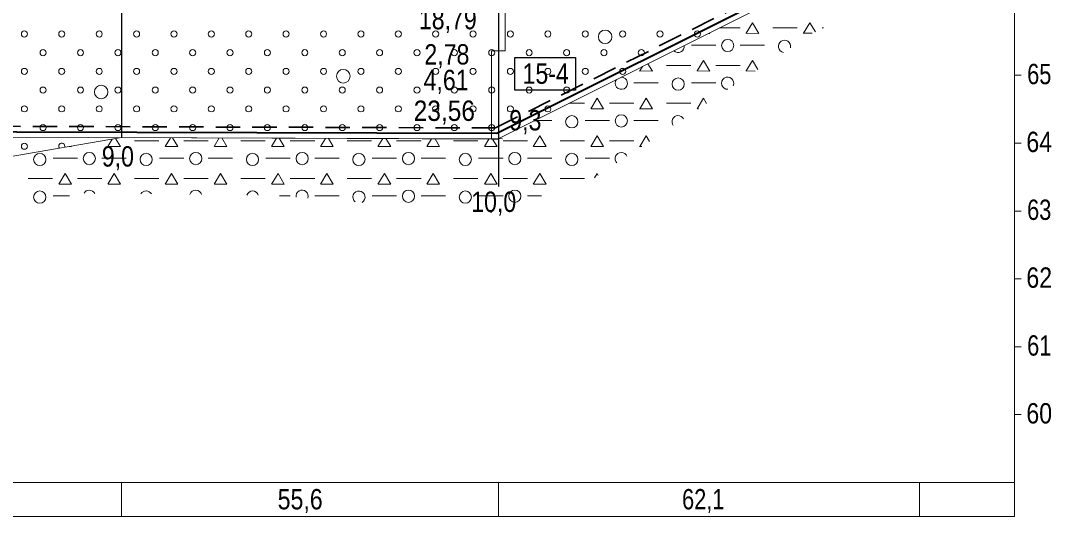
# Model space of a CAD drawing. Extents: x 640121 to 640955, y 6441885 to 6442246.
# Drawn here: x 640363.9 to 640515.9, y 6442063 to 6442136.1 of the extents above; entities that cross this region are included whole.
import ezdxf
from ezdxf.enums import TextEntityAlignment as Align

# ---------------------------------------------------------------- set-up
doc = ezdxf.new("R2010")
doc.units = 0
doc.header["$LTSCALE"] = 1.2
doc.linetypes.add('MEDIUM_DASHED', pattern=[4.5, 3, -1.5])
for name, color, linetype, lineweight in [('30', 7, 'Continuous', 13), ('31', 7, 'Continuous', 13), ('32', 7, 'Continuous', 13), ('33', 7, 'Continuous', 13), ('35', 7, 'Continuous', 35), ('42', 7, 'Continuous', 13), ('46', 7, 'Continuous', 13), ('47', 7, 'Continuous', 13)]:
    doc.layers.add(name, color=color, linetype=linetype, lineweight=lineweight)

msp = doc.modelspace()

# ---------------------------------------------------------------- linework, layer by layer
at = {"layer": '30'}
for p, q in [((640510.5, 6442063), (640510.5, 6442218)), ((640510.5, 6442128), (640511.5, 6442128)), ((640510.5, 6442118), (640511.5, 6442118)), ((640510.5, 6442108), (640511.5, 6442108)), ((640510.5, 6442098), (640511.5, 6442098)), ((640510.5, 6442088), (640511.5, 6442088)), ((640510.5, 6442078), (640511.5, 6442078)), ((640132.09, 6442068), (640510.5, 6442068)), ((640378.77, 6442068), (640378.77, 6442063)), ((640434.37, 6442068), (640434.37, 6442063)), ((640496.47, 6442068), (640496.47, 6442063)), ((640132.09, 6442063), (640510.5, 6442063))]:
    msp.add_line(p, q, dxfattribs=at)
at = {"layer": '31'}
msp.add_lwpolyline([(640156.71, 6442084.57), (640169.39, 6442084.94), (640174.39, 6442085), (640185.27, 6442085.01), (640198.57, 6442085.15), (640211.29, 6442085.53), (640222.23, 6442086.04), (640236.05, 6442086.58), (640247.59, 6442087.26), (640261.87, 6442089), (640272.13, 6442093.03), (640281.27, 6442096.49), (640290.79, 6442099.48), (640306.37, 6442104.48), (640328.11, 6442110.01), (640342.33, 6442112.86), (640361.6, 6442115.89), (640378.77, 6442118.83), (640434.25, 6442118.61), (640476.5, 6442139.76), (640496.42, 6442148.93), (640502.36, 6442149.59), (640510.5, 6442150.13)], dxfattribs=at)
at = {"layer": '32', "lineweight": 25}
for p, q in [((640434.37, 6442211.6), (640434.37, 6442111.6)), ((640378.77, 6442207.95), (640378.77, 6442118.83))]:
    msp.add_line(p, q, dxfattribs=at)
at = {"layer": '33'}
for points in [[(640435.37, 6442131.6), (640435.37, 6442146.6), (640434.36, 6442146.6), (640434.37, 6442131.6)], [(640433.37, 6442131.6), (640433.37, 6442118.6), (640434.37, 6442118.6), (640434.37, 6442131.6)]]:
    msp.add_lwpolyline(points, close=True, dxfattribs=at)
at = {"layer": '33', "lineweight": 25}
msp.add_lwpolyline([(640436.8, 6442130.61), (640445.73, 6442130.61), (640445.73, 6442125.83), (640436.8, 6442125.83)], close=True, dxfattribs=at)
at = {"layer": '35', "linetype": 'MEDIUM_DASHED'}
for points in [[(640433.96, 6442120.25), (640475.81, 6442141.2), (640494.87, 6442149.98)], [(640260.27, 6442115.49), (640327.87, 6442120.59), (640433.96, 6442120.25)]]:
    msp.add_lwpolyline(points, dxfattribs=at)
at = {"layer": '35', "lineweight": 40}
for points in [[(640434.15, 6442119.45), (640476.16, 6442140.48), (640495.67, 6442149.47)], [(640261.07, 6442114.75), (640327.9, 6442119.79), (640434.15, 6442119.45)]]:
    msp.add_lwpolyline(points, dxfattribs=at)
at = {"layer": '35', "lineweight": 13}
msp.add_lwpolyline([(640261.87, 6442114.01), (640327.93, 6442118.99), (640434.96, 6442118.65)], dxfattribs=at)
at = {"layer": '42'}
for centre in [(640364.45, 6442134.089), (640369.966, 6442134.089), (640375.481, 6442134.089), (640380.997, 6442134.089), (640386.512, 6442134.089), (640392.027, 6442134.089), (640397.543, 6442134.089), (640403.058, 6442134.089), (640408.574, 6442134.089), (640414.089, 6442134.089), (640419.605, 6442134.089), (640425.12, 6442134.089), (640430.636, 6442134.089), (640436.151, 6442134.089), (640441.666, 6442134.089), (640447.182, 6442134.089), (640452.697, 6442134.089), (640458.213, 6442134.089), (640463.728, 6442134.089), (640367.208, 6442131.332), (640372.723, 6442131.332), (640378.239, 6442131.332), (640383.754, 6442131.332), (640389.27, 6442131.332), (640394.785, 6442131.332), (640400.301, 6442131.332), (640405.816, 6442131.332), (640411.332, 6442131.332), (640416.847, 6442131.332), (640422.362, 6442131.332), (640427.878, 6442131.332), (640433.393, 6442131.332), (640438.909, 6442131.332), (640444.424, 6442131.332), (640449.94, 6442131.332), (640455.455, 6442131.332), (640364.45, 6442128.574), (640369.966, 6442128.574), (640375.481, 6442128.574), (640380.997, 6442128.574), (640386.512, 6442128.574), (640392.027, 6442128.574), (640397.543, 6442128.574), (640403.058, 6442128.574), (640408.574, 6442128.574), (640414.089, 6442128.574), (640419.605, 6442128.574), (640425.12, 6442128.574), (640430.636, 6442128.574), (640436.151, 6442128.574), (640441.666, 6442128.574), (640447.182, 6442128.574), (640452.697, 6442128.574), (640367.208, 6442125.816), (640372.723, 6442125.816), (640378.239, 6442125.816), (640383.754, 6442125.816), (640389.27, 6442125.816), (640394.785, 6442125.816), (640400.301, 6442125.816), (640405.816, 6442125.816), (640411.332, 6442125.816), (640416.847, 6442125.816), (640422.362, 6442125.816), (640427.878, 6442125.816), (640433.393, 6442125.816), (640438.909, 6442125.816), (640444.424, 6442125.816), (640364.45, 6442123.059), (640369.966, 6442123.059), (640375.481, 6442123.059), (640380.997, 6442123.059), (640386.512, 6442123.059), (640392.027, 6442123.059), (640397.543, 6442123.059), (640403.058, 6442123.059), (640408.574, 6442123.059), (640414.089, 6442123.059), (640419.605, 6442123.059), (640425.12, 6442123.059), (640430.636, 6442123.059), (640436.151, 6442123.059), (640441.666, 6442123.059), (640367.208, 6442120.301), (640372.723, 6442120.301), (640378.239, 6442120.301), (640383.754, 6442120.301), (640389.27, 6442120.301), (640394.785, 6442120.301), (640400.301, 6442120.301), (640405.816, 6442120.301), (640411.332, 6442120.301), (640416.847, 6442120.301), (640422.362, 6442120.301), (640427.878, 6442120.301), (640433.393, 6442120.301), (640364.45, 6442117.543)]:
    msp.add_circle(centre, 0.45, dxfattribs=at)
msp.add_arc((640369.966, 6442117.543), 0.45, 341.17001, 218.2282, dxfattribs=at)
at = {"layer": '46'}
for p, q in [((640470.05, 6442135), (640466.99, 6442135)), ((640478.45, 6442135), (640474.85, 6442135)), ((640480.68, 6442134.19), (640479.46, 6442134.19)), ((640482.35, 6442135), (640482.14, 6442135)), ((640466.45, 6442132.44), (640462.85, 6442132.44)), ((640473.65, 6442132.44), (640470.05, 6442132.44)), ((640462.75, 6442129.45), (640459.15, 6442129.45)), ((640470.05, 6442129.44), (640466.45, 6442129.44)), ((640472.27, 6442128.63), (640470.99, 6442128.64)), ((640457.95, 6442126.88), (640454.35, 6442126.88)), ((640466.45, 6442126.89), (640462.85, 6442126.89)), ((640447.06, 6442123.89), (640444.8, 6442123.89)), ((640454.35, 6442123.89), (640450.75, 6442123.89)), ((640462.75, 6442123.89), (640459.15, 6442123.89)), ((640463.91, 6442123.08), (640463.77, 6442123.08)), ((640442.26, 6442121.33), (640439.68, 6442121.33)), ((640450.75, 6442121.33), (640447.15, 6442121.33)), ((640457.95, 6442121.33), (640454.35, 6442121.33)), ((640375.88, 6442118.33), (640375.86, 6442118.33)), ((640384.28, 6442118.34), (640380.68, 6442118.34)), ((640391.57, 6442118.33), (640387.97, 6442118.33)), ((640399.97, 6442118.34), (640396.37, 6442118.34)), ((640407.27, 6442118.33), (640403.67, 6442118.33)), ((640415.67, 6442118.34), (640412.07, 6442118.34)), ((640422.96, 6442118.33), (640419.36, 6442118.33)), ((640431.36, 6442118.34), (640427.76, 6442118.34)), ((640438.66, 6442118.33), (640435.06, 6442118.33)), ((640447.06, 6442118.34), (640443.46, 6442118.34)), ((640454.35, 6442118.33), (640450.75, 6442118.33)), ((640455.54, 6442117.53), (640455.29, 6442117.53)), ((640372.28, 6442115.78), (640368.68, 6442115.78)), ((640379.48, 6442115.77), (640375.88, 6442115.77)), ((640387.97, 6442115.78), (640384.37, 6442115.78)), ((640395.17, 6442115.77), (640391.57, 6442115.77)), ((640403.67, 6442115.78), (640400.07, 6442115.78)), ((640410.87, 6442115.77), (640407.27, 6442115.77)), ((640419.36, 6442115.78), (640415.76, 6442115.78)), ((640426.56, 6442115.77), (640422.96, 6442115.77)), ((640435.06, 6442115.78), (640431.46, 6442115.78)), ((640442.26, 6442115.77), (640438.66, 6442115.77)), ((640450.75, 6442115.78), (640447.15, 6442115.78)), ((640368.58, 6442112.78), (640364.98, 6442112.78)), ((640375.88, 6442112.78), (640372.28, 6442112.78)), ((640384.28, 6442112.78), (640380.68, 6442112.78)), ((640391.57, 6442112.78), (640387.97, 6442112.78)), ((640399.97, 6442112.78), (640396.37, 6442112.78)), ((640407.27, 6442112.78), (640403.67, 6442112.78)), ((640415.67, 6442112.78), (640412.07, 6442112.78)), ((640422.96, 6442112.78), (640419.36, 6442112.78)), ((640431.36, 6442112.78), (640427.76, 6442112.78)), ((640438.66, 6442112.78), (640435.06, 6442112.78)), ((640447.06, 6442112.78), (640443.46, 6442112.78)), ((640371.09, 6442110.22), (640368.68, 6442110.22)), ((640403.67, 6442110.22), (640402.06, 6442110.22)), ((640410.87, 6442110.22), (640407.27, 6442110.22)), ((640419.36, 6442110.22), (640415.76, 6442110.22)), ((640426.56, 6442110.22), (640422.96, 6442110.22)), ((640435.06, 6442110.22), (640431.46, 6442110.22)), ((640440.75, 6442110.22), (640438.66, 6442110.22))]:
    msp.add_line(p, q, dxfattribs=at)
for points in [[(640470.91, 6442134.17), (640470.91, 6442134.19), (640471.86, 6442135.72), (640472.79, 6442134.18), (640470.99, 6442134.19)], [(640479.38, 6442134.17), (640479.38, 6442134.19), (640480.33, 6442135.72), (640481.13, 6442134.4)], [(640465.52, 6442134.26), (640465.57, 6442134.18), (640465.37, 6442134.18)], [(640456.44, 6442129.71), (640457.09, 6442128.63), (640455.29, 6442128.64)], [(640463.69, 6442128.61), (640463.69, 6442128.64), (640464.64, 6442130.17), (640465.57, 6442128.63), (640463.77, 6442128.64)], [(640470.91, 6442128.61), (640470.91, 6442128.64), (640471.86, 6442130.17), (640472.64, 6442128.87)], [(640455.21, 6442128.61), (640455.22, 6442128.64), (640455.63, 6442129.31)], [(640447.99, 6442123.06), (640447.99, 6442123.08), (640448.94, 6442124.61), (640449.87, 6442123.07), (640448.07, 6442123.08)], [(640455.21, 6442123.06), (640455.22, 6442123.08), (640456.16, 6442124.61), (640457.09, 6442123.07), (640455.29, 6442123.08)], [(640463.69, 6442123.06), (640463.69, 6442123.08), (640464.64, 6442124.61), (640465.09, 6442123.86)], [(640439.52, 6442117.51), (640439.52, 6442117.53), (640440.47, 6442119.06), (640441.4, 6442117.52), (640439.6, 6442117.53)], [(640447.99, 6442117.51), (640447.99, 6442117.53), (640448.94, 6442119.06), (640449.87, 6442117.52), (640448.07, 6442117.53)], [(640455.21, 6442117.51), (640455.22, 6442117.53), (640456.16, 6442119.06), (640456.64, 6442118.26)], [(640371.37, 6442117.56), (640371.4, 6442117.52), (640371.11, 6442117.52)], [(640376.74, 6442117.51), (640376.74, 6442117.53), (640377.4, 6442118.6)], [(640377.91, 6442118.68), (640378.62, 6442117.52), (640376.82, 6442117.53)], [(640385.21, 6442117.51), (640385.21, 6442117.53), (640386, 6442118.8)], [(640386.32, 6442118.8), (640387.09, 6442117.52), (640385.29, 6442117.53)], [(640392.43, 6442117.51), (640392.43, 6442117.53), (640393.2, 6442118.77)], [(640393.56, 6442118.77), (640394.31, 6442117.52), (640392.51, 6442117.53)], [(640400.91, 6442117.51), (640400.91, 6442117.53), (640401.66, 6442118.74)], [(640402.05, 6442118.74), (640402.79, 6442117.52), (640400.99, 6442117.53)], [(640408.13, 6442117.51), (640408.13, 6442117.53), (640408.86, 6442118.71)], [(640409.29, 6442118.71), (640410.01, 6442117.52), (640408.21, 6442117.53)], [(640416.6, 6442117.51), (640416.6, 6442117.53), (640417.31, 6442118.68)], [(640417.78, 6442118.67), (640418.48, 6442117.52), (640416.68, 6442117.53)], [(640423.82, 6442117.51), (640423.83, 6442117.53), (640424.52, 6442118.65)], [(640425.02, 6442118.64), (640425.7, 6442117.52), (640423.9, 6442117.53)], [(640432.3, 6442117.51), (640432.3, 6442117.53), (640432.97, 6442118.61)], [(640433.52, 6442118.61), (640434.18, 6442117.52), (640432.38, 6442117.53)], [(640369.51, 6442111.95), (640369.52, 6442111.97), (640370.47, 6442113.51), (640371.4, 6442111.96), (640369.6, 6442111.97)], [(640376.74, 6442111.95), (640376.74, 6442111.97), (640377.69, 6442113.51), (640378.62, 6442111.96), (640376.82, 6442111.97)], [(640385.21, 6442111.95), (640385.21, 6442111.97), (640386.16, 6442113.51), (640387.09, 6442111.96), (640385.29, 6442111.97)], [(640392.43, 6442111.95), (640392.43, 6442111.97), (640393.38, 6442113.51), (640394.31, 6442111.96), (640392.51, 6442111.97)], [(640400.91, 6442111.95), (640400.91, 6442111.97), (640401.86, 6442113.51), (640402.79, 6442111.96), (640400.99, 6442111.97)], [(640408.13, 6442111.95), (640408.13, 6442111.97), (640409.08, 6442113.51), (640410.01, 6442111.96), (640408.21, 6442111.97)], [(640416.6, 6442111.95), (640416.6, 6442111.97), (640417.55, 6442113.51), (640418.48, 6442111.96), (640416.68, 6442111.97)], [(640423.82, 6442111.95), (640423.83, 6442111.97), (640424.77, 6442113.51), (640425.7, 6442111.96), (640423.9, 6442111.97)], [(640432.3, 6442111.95), (640432.3, 6442111.97), (640433.25, 6442113.51), (640434.18, 6442111.96), (640432.38, 6442111.97)], [(640439.52, 6442111.95), (640439.52, 6442111.97), (640440.47, 6442113.51), (640441.4, 6442111.96), (640439.6, 6442111.97)], [(640448.57, 6442112.91), (640448.94, 6442113.51), (640449.09, 6442113.25)], [(640433.16, 6442107.81), (640433.25, 6442107.95), (640433.34, 6442107.79)]]:
    msp.add_lwpolyline(points, dxfattribs=at)
for centre in [(640468.196, 6442132.39), (640460.883, 6442126.714), (640445.188, 6442121.159), (640452.501, 6442121.282), (640366.712, 6442115.605), (640374.025, 6442115.727), (640382.407, 6442115.605), (640389.72, 6442115.727), (640398.102, 6442115.605), (640405.415, 6442115.727), (640413.797, 6442115.605), (640421.11, 6442115.727), (640429.492, 6442115.605), (640436.805, 6442115.727), (640445.188, 6442115.605), (640366.712, 6442110.051), (640421.11, 6442110.173), (640429.492, 6442110.051), (640436.805, 6442110.173)]:
    msp.add_circle(centre, 0.9, dxfattribs=at)
for centre, start, end in [((640476.578, 6442132.268), 347.17046, 259.94745), ((640460.883, 6442132.268), 225.70894, 7.46614), ((640452.501, 6442126.836), 142.22169, 90.95339), ((640468.196, 6442126.836), 336.12864, 270.98928), ((640460.883, 6442121.159), 29.05359, 218.06432), ((640452.501, 6442115.727), 22.18238, 224.93553), ((640374.025, 6442110.173), 28.72461, 150.00221), ((640382.407, 6442110.051), 30.86764, 147.85917), ((640389.72, 6442110.173), 16.61437, 162.11244), ((640398.102, 6442110.051), 18.5597, 160.16711), ((640405.415, 6442110.173), 342.16733, 188.95018), ((640413.797, 6442110.051), 300.72504, 230.39247)]:
    msp.add_arc(centre, 0.9, start, end, dxfattribs=at)
at = {"layer": '47'}
for centre in [(640450.114, 6442133.672), (640411.492, 6442127.864), (640375.775, 6442125.541)]:
    msp.add_circle(centre, 1, dxfattribs=at)

# ---------------------------------------------------------------- texts
at = {"layer": '30'}
for s, width, p in [('65', 0.8, (640514.16, 6442126.69)), ('64', 0.85, (640514.15, 6442116.69)), ('63', 0.8, (640514.15, 6442106.69)), ('62', 0.85, (640514.15, 6442096.69)), ('61', 0.8, (640514.155, 6442086.69)), ('60', 0.85, (640514.15, 6442076.69)), ('55,6', 0.85, (640405.13, 6442064.03)), ('62,1', 0.8, (640464.59, 6442064.03))]:
    msp.add_text(s, height=3, dxfattribs=dict(at, width=width)).set_placement(p, align=Align.CENTER)
at = {"layer": '32'}
for s, width, p in [('18,79', 0.85, (640426.91, 6442134.78)), ('2,78', 0.85, (640426.77, 6442129.59)), ('23,56', 0.9, (640426.395, 6442121.28)), ('9,3', 0.85, (640438.345, 6442119.88)), ('9,0', 0.85, (640378.24, 6442114.55)), ('10,0', 0.85, (640433.68, 6442107.86))]:
    msp.add_text(s, height=3, dxfattribs=dict(at, width=width)).set_placement(p, align=Align.CENTER)
at = {"layer": '33', "width": 0.85}
for s, p in [('15-4', (640441.345, 6442126.75)), ('4,61', (640426.655, 6442125.81))]:
    msp.add_text(s, height=3, dxfattribs=at).set_placement(p, align=Align.CENTER)

doc.saveas('drawing.dxf')
